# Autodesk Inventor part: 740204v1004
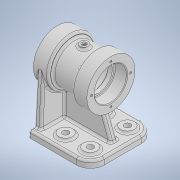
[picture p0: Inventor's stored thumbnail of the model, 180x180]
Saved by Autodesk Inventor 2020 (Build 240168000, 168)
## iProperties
Created: 2024-02
Part Number: 740204v1004
Material: 일반
Document SubType Name: Modeling
Designer: oem
Density: 1 g/cm^3
Appearance: 기본값
Author: oem
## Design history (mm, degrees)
sketch "스케치1"
  geometry: L1 (0, 0)-(22, 0); L2 (22, 0)-(22, 35); L3 (22, 35)-(0, 35); L4 (0, 35)-(0, 0); L5 (22, 0)-(56, 0); L6 (56, 0)-(56, 28.5); L7 (56, 28.5)-(22, 28.5); L8 (22, 28.5)-(22, 0); L9 (56, 0)-(78, 0); L10 (78, 0)-(78, 35); L11 (78, 35)-(56, 35); L12 (56, 35)-(56, 0); 2 further points
  constraints: 24 end point, 6 parallel, 3 horizontal, 3 perpendicular, 1 point on line
  dimensions: "d0" = 70 diameter of L3 L1; "d1" = 57 diameter of L7 L5; "d2" = 22 distance of L2.end L3.end; "d3" = 22 distance of L10.end L11.end; "d4" = 78 distance between parallel lines of L10 L4
revolve "회전1" sketch "스케치1" stored, may be unused: angle "d5" = 90 deg
sketch "스케치2"
  geometry: L1 (0, -35)-(0, 35) reference; L2 (78, -35)-(78, 35) reference; L3 (0, 0)-(18, 0); L4 (18, 0)-(18, 23.5); L5 (18, 23.5)-(0, 23.5); L6 (0, 23.5)-(0, 0); L7 (18, 0)-(24, 0); L8 (24, 0)-(24, 20); L9 (24, 20)-(18, 20); L10 (18, 20)-(18, 0); L11 (24, 0)-(54, 0); L12 (54, 0)-(54, 23.5); L13 (54, 23.5)-(24, 23.5); L14 (24, 23.5)-(24, 0); L15 (54, 0)-(60, 0); L16 (60, 0)-(60, 20); L17 (60, 20)-(54, 20); L18 (54, 20)-(54, 0); L19 (60, 0)-(78, 0); L20 (78, 0)-(78, 23.5); L21 (78, 23.5)-(60, 23.5); L22 (60, 23.5)-(60, 0); 6 further points
  constraints: 40 end point, 10 parallel, 5 horizontal, 5 perpendicular, 3 point on line
  dimensions: "d6" = 47 diameter of L5 L3; "d7" = 40 diameter of L9 L7; "d8" = 47 diameter of L13 L11; "d9" = 18 distance of L4.end L5.end; "d10" = 18 distance of L20.end L21.end; "d11" = 24 distance between parallel lines of L8 L1; "d12" = 24 distance between parallel lines of L18 L2
revolve "회전2" sketch "스케치2" stored, may be unused: angle "d13" = 90 deg
node "작업 평면1"
sketch "스케치3"
  geometry: L1 (0, 35)-(0, -35) reference; L2 (-5, -47)-(-95, -47); L3 (-95, -47)-(-95, 47); L4 (-95, 47)-(-5, 47); L5 (-5, 47)-(-5, -47); 1 further point
  constraints: 8 end point, 2 parallel, 1 horizontal, 1 perpendicular
  dimensions: "d15" = 5 distance between parallel lines of L5 L1; "d16" = 90 distance between parallel lines of L3 L5; "d17" = 47 distance from line of L4 point (0, 0); "d18" = 94 distance of L2.end L3.end
extrude "돌출1" join sketch "스케치3" distance "d19" = 10; taper "d20" = 0 deg
sketch "스케치6"
  geometry: L1 (0, 10)-(94, 10) reference; L2 (8, 10)-(12.055, 81.969); L3 (86, 10)-(81.945, 81.969); L4 (8, 10)-(86, 10); 4 further points
  constraints: 6 end point, 2 point on line, 1 horizontal, 6 other
  dimensions: "d24" = 8 distance of L2.start L1.start; "d25" = 8 distance of L3.start L1.end
extrude "돌출2" join sketch "스케치6" distance "d26" = 10; taper "d27" = 0 deg
sketch "스케치7"
  geometry: L1 (95, -70)-(5, -70) reference; L2 (83, -70)-(66.656, -25.096); L3 (66.656, -25.096)-(13.205, -25.096); L4 (15, -35)-(15, 1.969) reference; L5 (13.205, -25.096)-(13.205, -70); 1 further point
  constraints: 6 end point, 2 perpendicular, 2 point on line
  dimensions: "d28" = 12 distance of L2.start L1.start; "d29" = 70 deg angle of L2 L1
extrude "돌출3" join sketch "스케치7" stored distance "d30" = 10; taper "d31" = 0 deg
node "작업 평면3"
  node "작업 평면2"
sketch "스케치9"
  geometry: L1 (0, 35)-(0, -35) reference; C1 r 6 at (-39, 0); 1 further point
  constraints: 1 centre point
  dimensions: "d38" = 12 diameter of C1; "d39" = 39 distance from line of C1.centre L1
extrude "돌출5" join sketch "스케치9" stored distance "d40" = 3; taper "d41" = 0 deg
sketch "스케치10"
  geometry: L1 (5, 47)-(5, -47) reference; C1 r 10 at (39, -27); C2 r 10 at (75, -27); C3 r 10 at (39, 27); C4 r 10 at (75, 27); 1 further point
  constraints: 4 centre point
  dimensions: "d42" = 20 diameter of C1; "d43" = 20 diameter of C2; "d45" = 20 diameter of C3; "d46" = 20 diameter of C4; "d47" = 34 distance from line of C1.centre L1; "d48" = 36 distance of C2.centre C1.centre; "d49" = 34 distance from line of L1 C3.centre; "d50" = 36 distance of C4.centre C3.centre; "d51" = 27 vertical distance of C4.centre point (0, 0); "d52" = 54 distance of C2.centre C4.centre; "d53" = 27 vertical distance of C3.centre point (0, 0); "d54" = 54 distance of C3.centre C1.centre
extrude "돌출6" join sketch "스케치10" distance "d55" = 3; taper "d56" = 0 deg
sketch "스케치11"
  geometry: C1 r 10 at (0, 0) reference; C2 r 10 at (0, 54) reference; C3 r 10 at (36, 54) reference; C4 r 10 at (36, 0) reference; C5 r 4.5 at (0, 0); C6 r 4.5 at (36, 0); C7 r 4.5 at (36, 54); C8 r 4.5 at (0, 54); 1 further point
  constraints: 4 centre point, 4 coincident
  dimensions: "d57" = 9 diameter of C5; "d58" = 9 diameter of C6; "d59" = 9 diameter of C7; "d60" = 9 diameter of C8
extrude "돌출7" cut sketch "스케치11" extent not by distance; stored distance "d61" = 76.124; taper "d62" = 0 deg
fillet "모깎기1" dims "d63" = 20
sketch "스케치12"
  geometry: C1 r 6 at (0, 0) reference; 2 further points
  constraints: 1 coincident
hole "구멍1" sketch "스케치12" at (0, 0) diameter "d64" = 5.1881; stored, may be unused: countersink angle "d68" = 90 deg, drill point angle "d70" = 118 deg; dims "d65" = 20, "d66" = 7, "d67" = 2, "d69" = 20
sketch "스케치13"
  geometry: C1 r 35 at (0, 0) reference; A1 r 28.5 centre (0, 0) between (0, 28.5) and (-28.5, 0); A2 r 28.5 centre (0, 0) between (5, -28.058) and (-5, -28.058) reference; 2 further points
  constraints: 4 point on circle, 1 centre point, 1 coincident
  dimensions: "d71" = 57 diameter of A1
hole "구멍2" sketch "스케치13" at (0, 28.5), (-28.5, 0), (0, -28.5), (28.5, 0) diameter "d72" = 3.242; stored, may be unused: countersink angle "d76" = 90 deg, drill point angle "d78" = 118 deg; dims "d73" = 8, "d74" = 7, "d75" = 2, "d77" = 10
node "작업 평면4"
fillet "모깎기2" dims "d79" = 1
fillet "모깎기4" dims "d81" = 3
chamfer "모따기1" distance "d83" = 1; stored, may be unused: second distance "d84" = 2, angle "d85" = 45 deg
fillet "모깎기6" dims "d86" = 3
fillet "모깎기7" dims "d87" = 3
fillet "모깎기8" dims "d88" = 3
fillet "모깎기9" dims "d89" = 3
fillet "모깎기10" dims "d90" = 3
sketch "스케치14"
  geometry: L1 (0, 0)-(88, 0) reference; L2 (23.555, 23.567)-(65.034, 23.567); L3 (65.034, 23.567)-(65.034, 17.563); L4 (65.034, 17.563)-(23.555, 17.563); L5 (23.555, 17.563)-(23.555, 23.567); L6 (22.087, 20)-(61.766, 20); L7 (44, 80)-(44, -11.434); A1 r 38 centre (44, 80) between (10.898, 61.339) and (77.102, 61.339) reference
  constraints: 4 end point, 1 horizontal, 1 vertical, 2 other
  dimensions: "d91" = 20 distance between parallel lines of L6 L1
feature "엠보싱1" sketch "스케치14" dims "d0" = 70, "d1" = 57, "d2" = 22, "d3" = 22, "d4" = 78, "d6" = 47, "d7" = 40, "d8" = 47, "d9" = 18, "d10" = 18, "d11" = 24, "d12" = 24, "d92" = 0.5, "d93" = 0
fillet "모깎기11" dims "d94" = 3
node "솔리드1"
mirror "미러1"
feature "A9D066F2-1C7D-4E18-AEED-F7BC21143FA4" dims "d64" = 5.1881, "d65" = 20, "d66" = 7, "d67" = 2, "d68" = 90 deg, "d69" = 20, "d70" = 118 deg
other parameters: "d32" = 28.5, "d37" = 3
